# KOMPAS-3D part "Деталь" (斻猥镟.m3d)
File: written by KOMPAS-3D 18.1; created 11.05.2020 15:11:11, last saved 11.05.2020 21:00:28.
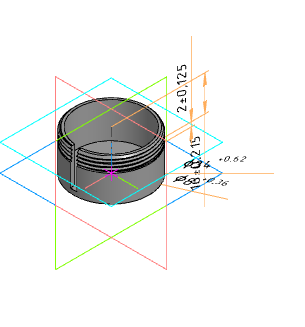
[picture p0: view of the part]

Document properties: Автор: yarkov_aleksei@mail.ru; Полное имя файла: C:\Users\Leha\Desktop\Футляр для швейного метра\Футляр.m3d

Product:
- Part/product: Деталь
    Материал: Фторопласт-4  ГОСТ 10007-80 Е (density 2200 kg/m3)
    Масса: 0.00998055

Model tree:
1. Смещенная плоскость:1
     Расстояние = 12
2. Эскиз:3
3. Элемент выдавливания:2
     Расстояние 1 = 6
4. Фаска:1  (with: Элемент выдавливания:2)
     Угол = 45; Длина 1 = 1; Длина 2 = 1
5. Эскиз:4
6. Спираль:1
     Число витков = 15; Шаг = 1.5; Высота = 22.5; Диаметр 1 = 34; Диаметр 2 = 10
7. Эскиз:6
8. Элемент по траектории:1
9. Эскиз:7  (with: Элемент выдавливания:2)
10. Элемент выдавливания:3
     Расстояние 1 = 12
11. Эскиз:8  (with: Элемент выдавливания:2, Фаска:1)
12. Элемент выдавливания:4
     Расстояние 2 = 16
13. Линейный размер:1  (with: Элемент выдавливания:4, Элемент выдавливания:2)
     Значение = 16
14. Эскиз:9  (with: Элемент выдавливания:4)
15. Элемент выдавливания:5
     Расстояние 2 = 2
16. Эскиз:10
17. Элемент выдавливания:6
     Расстояние 2 = 17
18. Диаметральный размер:1  (with: Элемент выдавливания:3)
     Значение = 34
19. Диаметральный размер:2  (with: Элемент выдавливания:5)
     Значение = 8
20. Линейный размер:2  (with: Элемент выдавливания:4, Элемент выдавливания:3)  (labels: Фторопласт-4  ГОСТ 10007-80 Е)
     Значение = 2

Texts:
  Точка начала. Х
  Точка начала. Y
  Точка начала. Z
